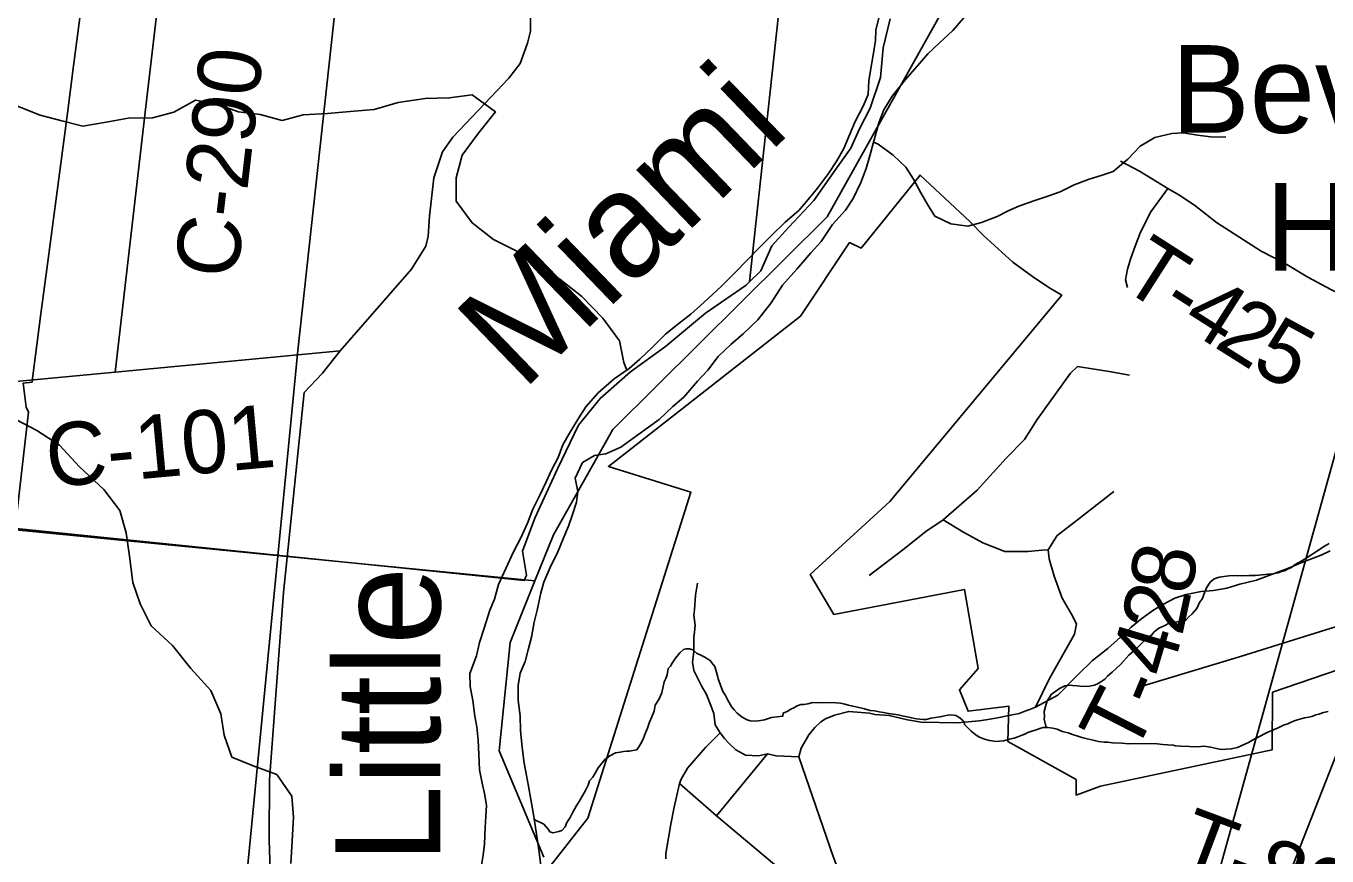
# Model space of a CAD drawing. Extents: x 44.2 to 78.2, y 4.5 to 26.5.
# Drawn here: x 49.189 to 50.361, y 22.487 to 23.234 of the extents above; entities that cross this region are included whole.
import ezdxf

# ---------------------------------------------------------------- set-up
doc = ezdxf.new("R2010")
doc.units = 0
for name, color, linetype in [('GM_X_City_Street', 7, 'Continuous'), ('GM_X_Corporation', 7, 'Continuous'), ('GM_X_County_Road', 7, 'Continuous'), ('GM_X_County_Road_Text', 7, 'Continuous'), ('GM_X_Interstate_Route', 7, 'Continuous'), ('GM_X_Major_River', 7, 'Continuous'), ('GM_X_Major_River_Text', 7, 'Continuous'), ('GM_X_Minor_River', 7, 'Continuous'), ('GM_X_Rail_Line', 7, 'Continuous'), ('GM_X_Section', 7, 'Continuous'), ('GM_X_State_Route', 7, 'Continuous'), ('GM_X_Township_Road', 7, 'Continuous'), ('GM_X_Township_Road_Text', 7, 'Continuous'), ('GM_X_Unincorporated_Text', 7, 'Continuous'), ('SH_Cut_Line', 7, 'Continuous'), ('SH_Data', 7, 'Continuous')]:
    doc.layers.add(name, color=color, linetype=linetype)

msp = doc.modelspace()

# ---------------------------------------------------------------- linework, layer by layer
at = {"layer": 'GM_X_City_Street'}
msp.add_line((49.8105, 22.5227), (49.8565, 22.5786), dxfattribs=at)
for points in [[(49.8849, 22.5759), (49.8643, 22.5767), (49.8565, 22.5786), (49.8485, 22.5768), (49.8366, 22.5774), (49.828, 22.582), (49.8215, 22.5883), (49.8177, 22.5923), (49.8138, 22.5974), (49.8094, 22.6046), (49.8083, 22.6148), (49.8055, 22.622), (49.8017, 22.632), (49.797, 22.6399), (49.7901, 22.6537), (49.7889, 22.6612), (49.7901, 22.6703), (49.7901, 22.6832), (49.7908, 22.6885), (49.7914, 22.6942), (49.7901, 22.7033), (49.7908, 22.7083), (49.7917, 22.7215), (49.7936, 22.7321)], [(49.765, 22.484), (49.765, 22.4866), (49.7651, 22.4887), (49.7695, 22.5153), (49.7724, 22.5306), (49.7773, 22.5519), (49.7787, 22.5558), (49.7844, 22.5656), (49.7923, 22.5747), (49.8009, 22.5844), (49.8138, 22.5974)], [(49.9367, 22.4306), (49.9156, 22.4861), (49.8849, 22.5759)], [(49.8798, 22.4648), (49.8105, 22.5227), (49.7773, 22.5519)]]:
    msp.add_lwpolyline(points, dxfattribs=at)
at = {"layer": 'GM_X_Corporation'}
msp.add_lwpolyline([(49.6269, 22.4341), (49.6947, 22.5207), (49.7875, 22.8141), (49.7133, 22.8372), (49.8862, 22.9727), (49.9305, 23.039), (49.9408, 23.034), (49.994, 23.0998), (50.0389, 23.0579), (50.0512, 23.0452), (50.0777, 23.0214), (50.0953, 23.0083), (50.11, 22.9986), (50.1216, 22.9917), (49.9668, 22.8059), (49.895, 22.7401), (49.9162, 22.7041), (50.0341, 22.7264), (50.0463, 22.6553), (50.0294, 22.6361), (50.0372, 22.6168), (50.0741, 22.6214), (50.0731, 22.5895), (50.1347, 22.5553), (50.1346, 22.5413), (50.1565, 22.5494), (50.3111, 22.582), (50.3116, 22.634), (50.3836, 22.6588)], dxfattribs=at)
at = {"layer": 'GM_X_County_Road'}
for points in [[(49.2689, 22.9223), (49.2965, 23.1616), (49.3169, 23.3355), (49.3208, 23.3684), (49.3292, 23.4402), (49.3295, 23.4424), (49.3374, 23.5063), (49.3403, 23.5298), (49.3454, 23.5703)], [(49.1987, 22.9157), (49.2689, 22.9223), (49.4717, 22.9416)], [(49.0413, 22.9008), (49.1987, 22.9157)], [(50.0894, 22.6171), (50.092, 22.6181), (50.098, 22.6206), (50.118, 22.6314), (50.1362, 22.6497), (50.1494, 22.6627), (50.1632, 22.6734), (50.1745, 22.6835), (50.1842, 22.6926), (50.1927, 22.6995), (50.2037, 22.7076), (50.2134, 22.7133), (50.2234, 22.7186), (50.2338, 22.7221), (50.2473, 22.7246), (50.2583, 22.7255), (50.2702, 22.7277), (50.2821, 22.7312), (50.2972, 22.7349), (50.3107, 22.74), (50.3245, 22.745), (50.3395, 22.7513), (50.3552, 22.7575), (50.3634, 22.7613)], [(49.8849, 22.5759), (49.8868, 22.5837), (49.8937, 22.5956), (49.8993, 22.6022), (49.9047, 22.6072), (49.9087, 22.6101), (49.9169, 22.6132), (49.9298, 22.6167), (49.9483, 22.615), (49.9532, 22.614), (49.9662, 22.6129), (49.9828, 22.6091), (49.995, 22.6069), (50.0276, 22.6063), (50.0473, 22.6081), (50.0533, 22.609), (50.0622, 22.6106), (50.0755, 22.6132), (50.0834, 22.6148), (50.0894, 22.6171)]]:
    msp.add_lwpolyline(points, dxfattribs=at)
at = {"layer": 'GM_X_Interstate_Route'}
msp.add_lwpolyline([(49.1786, 22.7786), (49.1909, 22.8861), (49.1887, 22.8907), (49.1861, 22.9124), (49.194, 22.9133), (49.1948, 22.9189), (49.202, 22.9747), (49.2079, 23.0194), (49.216, 23.0809), (49.2259, 23.1554), (49.2315, 23.1982), (49.2488, 23.3306)], dxfattribs=at)
at = {"layer": 'GM_X_Major_River'}
for points in [[(49.957, 23.2425), (49.9541, 23.2304), (49.9539, 23.2209), (49.9517, 23.2076), (49.9492, 23.194), (49.9478, 23.1845), (49.9472, 23.1723), (49.9428, 23.1618), (49.9356, 23.1479), (49.9308, 23.1366), (49.9252, 23.1238), (49.9189, 23.1125), (49.9115, 23.1012), (49.9017, 23.0881), (49.8931, 23.0777), (49.8849, 23.0679), (49.8725, 23.0572), (49.8601, 23.0453), (49.8504, 23.0356), (49.8376, 23.0225), (49.8279, 23.0125), (49.8151, 22.9998), (49.7992, 22.9849), (49.7876, 22.9745), (49.7756, 22.9653), (49.7648, 22.9564), (49.7528, 22.9444), (49.7416, 22.934), (49.7319, 22.9255), (49.7184, 22.9163), (49.7041, 22.9036), (49.6928, 22.8909), (49.6865, 22.8812), (49.6782, 22.8673), (49.6723, 22.8568), (49.6679, 22.8454), (49.6623, 22.8345), (49.6572, 22.8236), (49.6512, 22.8108), (49.6452, 22.7988), (49.6404, 22.7863), (49.6344, 22.7731), (49.6277, 22.7604), (49.6209, 22.7453), (49.6142, 22.731), (49.6105, 22.7178), (49.6064, 22.708), (49.6012, 22.6917), (49.5971, 22.6789), (49.5945, 22.6668), (49.5885, 22.6509), (49.5886, 22.6391), (49.591, 22.6265), (49.593, 22.6124), (49.5947, 22.6029), (49.5959, 22.5907), (49.5964, 22.5778), (49.5972, 22.5641), (49.5996, 22.5522), (49.6017, 22.5427), (49.6034, 22.5324), (49.6028, 22.5221), (49.6022, 22.5126), (49.6015, 22.4971), (49.6005, 22.4872), (49.5983, 22.4747)], [(49.6526, 22.4755), (49.6507, 22.4919), (49.6491, 22.5022), (49.6477, 22.5121), (49.6454, 22.5258), (49.6434, 22.5373), (49.6413, 22.5495), (49.6393, 22.559), (49.6372, 22.5701), (49.6356, 22.5842), (49.6341, 22.5994), (49.6336, 22.6127), (49.632, 22.6264), (49.6319, 22.6401), (49.6337, 22.6511), (49.6381, 22.6617), (49.641, 22.6723), (49.6439, 22.6836), (49.6465, 22.6972), (49.649, 22.7078), (49.6523, 22.7234), (49.6552, 22.7332), (49.6616, 22.7483), (49.6671, 22.7588), (49.6732, 22.7735), (49.6772, 22.7837), (49.6808, 22.7942), (49.6845, 22.8052), (49.6858, 22.8147), (49.6834, 22.8269), (49.6898, 22.8408), (49.7006, 22.8471), (49.7109, 22.8487), (49.7243, 22.8546), (49.7343, 22.8619), (49.759, 22.8797), (49.7714, 22.8912), (49.7811, 22.8998), (49.7935, 22.914), (49.8028, 22.924), (49.8122, 22.9364), (49.8235, 22.9472), (49.8347, 22.9568), (49.8479, 22.9695), (49.86, 22.9848), (49.8702, 23.0006), (49.883, 23.0151), (49.8955, 23.0297), (49.9048, 23.0398), (49.915, 23.0552), (49.9267, 23.0682), (49.9338, 23.0787), (49.9405, 23.093), (49.9453, 23.1058), (49.9486, 23.1172), (49.9527, 23.1315), (49.9569, 23.1467), (49.9613, 23.1584), (49.9688, 23.1708), (49.9809, 23.1857), (49.9918, 23.198), (50.0011, 23.2089), (50.0112, 23.2185), (50.0236, 23.2301), (50.0349, 23.2431)]]:
    msp.add_lwpolyline(points, dxfattribs=at)
at = {"layer": 'GM_X_Minor_River'}
for points in [[(49.7298, 22.9241), (49.727, 22.9311), (49.7232, 22.9505), (49.7083, 22.971), (49.6892, 22.9904), (49.6694, 23.006), (49.65, 23.0186), (49.6294, 23.0319), (49.6096, 23.0418), (49.5905, 23.0566), (49.576, 23.0764), (49.576, 23.0973), (49.5814, 23.1178), (49.5958, 23.1372), (49.6115, 23.1566), (49.5905, 23.1719), (49.5699, 23.1692), (49.5482, 23.1688), (49.5238, 23.165), (49.5021, 23.1589), (49.4807, 23.157), (49.4602, 23.1551), (49.4384, 23.154), (49.4194, 23.149), (49.3996, 23.1544), (49.3801, 23.1566), (49.3607, 23.1635), (49.3413, 23.1673), (49.3218, 23.1563), (49.3024, 23.1513), (49.2807, 23.1509), (49.2608, 23.1475), (49.2399, 23.1437), (49.2208, 23.1487), (49.2014, 23.1536), (49.1793, 23.1624)], [(49.9521, 23.1293), (49.9562, 23.1275), (49.9697, 23.1177), (49.9813, 23.1069), (49.9882, 23.0961), (49.9948, 23.0838), (50.0014, 23.0723), (50.0073, 23.0627), (50.0216, 23.0559), (50.0371, 23.0537), (50.0494, 23.0569), (50.0635, 23.0623), (50.0735, 23.0675), (50.0831, 23.0718), (50.0965, 23.0765), (50.1091, 23.0808), (50.1202, 23.0848), (50.1329, 23.091), (50.1463, 23.0961), (50.157, 23.0993), (50.168, 23.1029), (50.1812, 23.114), (50.1924, 23.1259), (50.2055, 23.1337), (50.2208, 23.1372), (50.231, 23.1377), (50.2439, 23.1356), (50.256, 23.1342), (50.2693, 23.134)], [(49.4271, 22.4796), (49.4282, 22.5001), (49.4294, 22.5214), (49.4279, 22.5404), (49.4145, 22.5598), (49.3932, 22.5678), (49.3741, 22.5754), (49.3672, 22.5952), (49.3642, 22.6146), (49.355, 22.6355), (49.3371, 22.6553), (49.3204, 22.6762), (49.3013, 22.6937), (49.2914, 22.7135), (49.2849, 22.7329), (49.2819, 22.7565), (49.2788, 22.7774), (49.2731, 22.7976), (49.2586, 22.8166), (49.2369, 22.8371), (49.2186, 22.8565), (49.1984, 22.8698), (49.1793, 22.8797)], [(50.1077, 22.6021), (50.1059, 22.6097), (50.106, 22.612), (50.1057, 22.6166), (50.107, 22.6211), (50.1086, 22.6263), (50.111, 22.6297), (50.1122, 22.6319), (50.1195, 22.6374), (50.1245, 22.6396), (50.1276, 22.6403), (50.1314, 22.6402), (50.1355, 22.6397), (50.1405, 22.6392), (50.1466, 22.6394), (50.1511, 22.6404), (50.1538, 22.6415), (50.1569, 22.6433), (50.1604, 22.6458), (50.1627, 22.6484), (50.167, 22.6521), (50.1744, 22.6591), (50.1822, 22.6673), (50.1869, 22.6717), (50.19, 22.6743), (50.1931, 22.6776), (50.1966, 22.6809), (50.2001, 22.6839), (50.2024, 22.6853), (50.2048, 22.6883), (50.209, 22.6916), (50.2144, 22.6941), (50.2179, 22.6959), (50.2224, 22.6969), (50.227, 22.6976), (50.2312, 22.6982), (50.2335, 22.6989), (50.2359, 22.7015), (50.239, 22.7045), (50.2433, 22.7093), (50.2461, 22.7153), (50.248, 22.7179), (50.2505, 22.7243), (50.2521, 22.728), (50.2553, 22.7332), (50.2588, 22.7362), (50.2634, 22.7376), (50.2675, 22.7382), (50.2721, 22.7389), (50.2778, 22.7391), (50.2843, 22.7389), (50.2904, 22.7391), (50.2961, 22.739), (50.3021, 22.7396), (50.3079, 22.7402), (50.312, 22.7405), (50.3162, 22.7415), (50.3197, 22.7426), (50.3224, 22.7432), (50.3251, 22.7447), (50.3281, 22.7461), (50.332, 22.7491), (50.3378, 22.7523), (50.3428, 22.7552), (50.347, 22.7581), (50.3505, 22.7603), (50.3582, 22.7654), (50.3625, 22.768)], [(49.6465, 22.5195), (49.655, 22.5153), (49.659, 22.5107), (49.6605, 22.5084), (49.6631, 22.5075), (49.6685, 22.5085), (49.6712, 22.5096), (49.6743, 22.5129), (49.6759, 22.5167), (49.6787, 22.5212), (49.6811, 22.526), (49.6842, 22.5313), (49.687, 22.5357), (49.6926, 22.5455), (49.695, 22.5503), (49.6962, 22.5541), (49.6993, 22.5574), (49.7013, 22.5612), (49.7041, 22.566), (49.71, 22.5734), (49.7146, 22.5767), (49.7196, 22.5793), (49.7238, 22.5799), (49.7269, 22.5806), (49.7299, 22.5809), (49.7322, 22.5808), (49.7353, 22.5815), (49.7387, 22.5822), (49.7407, 22.5848), (49.7434, 22.5893), (49.7447, 22.5926), (49.7467, 22.5975), (49.7483, 22.6016), (49.7503, 22.6069), (49.7524, 22.6118), (49.7544, 22.617), (49.7553, 22.6223), (49.7588, 22.6275), (49.7613, 22.6335), (49.7634, 22.6433), (49.765, 22.6463), (49.7662, 22.6497), (49.7671, 22.6554), (49.7691, 22.6576), (49.7707, 22.6602), (49.7738, 22.6647), (49.7777, 22.6695), (49.7809, 22.6725), (49.7832, 22.6732), (49.7862, 22.6731), (49.7892, 22.6722), (49.7925, 22.6691), (49.7971, 22.6671), (49.8001, 22.6655), (49.8027, 22.6639), (49.8049, 22.6627), (49.8064, 22.6604), (49.809, 22.6573), (49.8097, 22.655), (49.8107, 22.652), (49.8114, 22.6489), (49.8121, 22.6462), (49.8164, 22.6347), (49.8186, 22.6309), (49.8207, 22.6267), (49.8244, 22.6205), (49.8266, 22.6182), (49.8292, 22.6151), (49.8336, 22.6115), (49.8381, 22.6092), (49.8408, 22.6083), (49.8446, 22.6078), (49.8484, 22.6081), (49.8537, 22.6091), (49.8602, 22.6112), (49.8705, 22.6125), (49.8706, 22.6151), (49.8748, 22.6169), (49.8771, 22.6184), (49.8809, 22.6202), (49.8833, 22.6216), (49.8867, 22.623), (49.8894, 22.623), (49.8928, 22.6236), (49.8974, 22.6247), (49.9023, 22.6245), (49.9054, 22.6248), (49.9187, 22.6245), (49.9224, 22.624), (49.9262, 22.6232), (49.9296, 22.6223), (49.9334, 22.6214), (49.9402, 22.6198), (49.944, 22.6189), (49.9489, 22.6176), (49.953, 22.6171), (49.9572, 22.6163), (49.961, 22.6158), (49.9655, 22.6149), (49.9697, 22.6141), (49.9742, 22.6136)], [(49.9742, 22.6136), (49.978, 22.6127), (49.9825, 22.6118), (49.9863, 22.611), (49.9908, 22.6101), (49.9969, 22.6095), (49.9996, 22.6095), (50.0041, 22.6105), (50.0118, 22.6118), (50.0206, 22.6135), (50.024, 22.6134), (50.0262, 22.613), (50.0289, 22.6114), (50.0315, 22.6094), (50.0337, 22.6071), (50.034, 22.6048), (50.0362, 22.6028), (50.0399, 22.5989), (50.0444, 22.5954), (50.0474, 22.5934), (50.0519, 22.5918), (50.0564, 22.5906), (50.0625, 22.5896), (50.0655, 22.5899), (50.0693, 22.5902), (50.0747, 22.5916), (50.0789, 22.5926), (50.082, 22.5937), (50.085, 22.5951), (50.0889, 22.5965), (50.0912, 22.5976), (50.0939, 22.5987), (50.0985, 22.6001), (50.1027, 22.6015), (50.105, 22.6022), (50.1091, 22.6021), (50.1137, 22.6016), (50.1175, 22.6007), (50.122, 22.5987), (50.1273, 22.5974), (50.1314, 22.5958), (50.1352, 22.5946), (50.1397, 22.5933), (50.1446, 22.592), (50.1499, 22.5908), (50.1548, 22.5895), (50.1597, 22.589), (50.1631, 22.5889), (50.1673, 22.5884), (50.1756, 22.5882), (50.1821, 22.5876), (50.1878, 22.5879), (50.2075, 22.5874), (50.2128, 22.5868), (50.217, 22.5867), (50.2219, 22.5862), (50.2242, 22.5858), (50.2287, 22.5853), (50.2447, 22.5849), (50.247, 22.5852), (50.2496, 22.5855), (50.2557, 22.5846), (50.261, 22.5833), (50.2651, 22.5824), (50.2697, 22.5827), (50.2743, 22.583), (50.28, 22.5843), (50.2838, 22.5861), (50.2873, 22.5875), (50.29, 22.5886), (50.2935, 22.5908), (50.2973, 22.593), (50.3073, 22.598), (50.3165, 22.6019), (50.3219, 22.6045), (50.3254, 22.6055), (50.3284, 22.6069), (50.3319, 22.6084), (50.3361, 22.6098), (50.3403, 22.6108), (50.3441, 22.6115), (50.3479, 22.6125), (50.3506, 22.6136), (50.3533, 22.6143), (50.3575, 22.6157), (50.3617, 22.6167)]]:
    msp.add_lwpolyline(points, dxfattribs=at)
at = {"layer": 'GM_X_Rail_Line'}
for points in [[(49.3823, 22.417), (49.4335, 22.9419), (49.5157, 23.6948), (49.5516, 23.9481), (49.5607, 24.0404), (49.5582, 24.101), (49.5479, 24.1577), (49.5234, 24.2196), (49.4858, 24.2792), (49.3949, 24.3999)], [(47.6333, 22.932), (49.4237, 22.7563), (49.647, 22.7343), (49.6637, 22.7757), (49.7173, 22.8707), (49.9104, 23.0622), (50.0184, 23.2552)], [(50.0184, 23.2552), (49.9104, 23.0622), (49.7173, 22.8707), (49.6637, 22.7757), (49.647, 22.7343), (49.6246, 22.6788), (49.6147, 22.5812), (49.655, 22.4854)], [(49.655, 22.4854), (49.6147, 22.5812), (49.6246, 22.6788), (49.647, 22.7343), (49.4237, 22.7563), (47.6333, 22.932), (46.627, 23.0248), (46.3359, 23.0552), (46.3359, 19.3655)]]:
    msp.add_lwpolyline(points, dxfattribs=at)
at = {"layer": 'GM_X_Section'}
msp.add_lwpolyline([(48.7465, 23.8538), (49.9184, 23.7227), (49.8403, 23.0036), (49.8372, 23.0006), (49.8007, 22.9753), (49.7648, 22.9454), (49.7332, 22.9224), (49.7059, 22.8985), (49.6863, 22.8746), (49.6675, 22.8353), (49.647, 22.7909), (49.6359, 22.761), (49.6394, 22.7393), (49.6374, 22.7347), (48.6514, 22.8354)], close=True, dxfattribs=at)
msp.add_lwpolyline([(49.967, 23.2404), (49.9608, 23.2144), (49.9584, 23.1875), (49.9491, 23.16), (49.9392, 23.1409), (49.9317, 23.124), (49.9181, 23.105), (49.8982, 23.077), (49.8757, 23.0528), (49.8606, 23.0361), (49.8505, 23.0134), (49.8403, 23.0036), (49.9184, 23.7227)], dxfattribs=at)
at = {"layer": 'GM_X_State_Route'}
for points in [[(49.6431, 23.2489), (49.6429, 23.2295), (49.6402, 23.2186), (49.6336, 23.2003), (49.6235, 23.187), (49.602, 23.1641), (49.5732, 23.1338), (49.5639, 23.1206), (49.556, 23.0974), (49.5521, 23.0626), (49.5509, 23.0448), (49.5489, 23.0357), (49.5358, 23.015), (49.4717, 22.9416)], [(49.4717, 22.9416), (49.4556, 22.9214), (49.4392, 22.9039), (49.4239, 22.7557), (49.4206, 22.7237), (49.4078, 22.5555), (49.4076, 22.5011), (49.4086, 22.4737), (49.4079, 22.4509), (49.4003, 22.4227)]]:
    msp.add_lwpolyline(points, dxfattribs=at)
at = {"layer": 'GM_X_Township_Road'}
for points in [[(50.4459, 22.9631), (50.3904, 22.9835), (50.364, 22.9966), (50.3433, 23.0078), (50.3229, 23.0201), (50.3013, 23.0311), (50.2611, 23.0569), (50.2411, 23.0728), (50.2272, 23.0819), (50.2171, 23.0877), (50.1918, 23.1033), (50.1744, 23.1124)], [(50.2171, 23.0877), (50.2019, 23.0666), (50.1927, 23.0484), (50.1877, 23.0358), (50.1839, 23.0249), (50.1808, 23.0151), (50.1792, 23.0054), (50.1808, 22.9985)], [(49.9482, 22.739), (49.9785, 22.7621), (49.9991, 22.7786), (50.0147, 22.7893), (50.0455, 22.816), (50.0716, 22.8448), (50.0881, 22.8616), (50.0994, 22.8795), (50.1295, 22.9214), (50.1357, 22.9273), (50.1644, 22.9228), (50.1826, 22.9194)], [(50.098, 22.6206), (50.1106, 22.6465), (50.1264, 22.6746), (50.1332, 22.6864), (50.135, 22.6957), (50.1304, 22.7042), (50.1221, 22.7188), (50.1149, 22.7385), (50.1103, 22.7541), (50.1093, 22.7621), (50.1176, 22.7751), (50.1342, 22.788), (50.1686, 22.8148)], [(50.1093, 22.7621), (50.1037, 22.7619), (50.0914, 22.7608), (50.0703, 22.7607), (50.0505, 22.7684), (50.0326, 22.7783), (50.0147, 22.7893)], [(50.3738, 22.6946), (50.2825, 22.6663), (50.192, 22.6387)]]:
    msp.add_lwpolyline(points, dxfattribs=at)
at = {"layer": 'SH_Cut_Line'}
for points in [[(49.655, 22.4854), (49.6147, 22.5812), (49.6246, 22.6788), (49.647, 22.7343), (49.6637, 22.7757), (49.7173, 22.8707), (49.9104, 23.0622), (50.0184, 23.2552)], [(50.0184, 23.2552), (49.9104, 23.0622), (49.7173, 22.8707), (49.6637, 22.7757), (49.647, 22.7343), (49.6246, 22.6788), (49.6147, 22.5812), (49.655, 22.4854)]]:
    msp.add_lwpolyline(points, dxfattribs=at)
at = {"layer": 'SH_Data'}
msp.add_lwpolyline([(50.6141, 23.7345), (50.1075, 21.9122), (50.6141, 23.202)], close=True, dxfattribs=at)

# ---------------------------------------------------------------- texts
at = {"layer": 'GM_X_County_Road_Text'}
for s, rotation, p in [('C-290', 83.387, (49.3786, 23.0052)), ('C-101', 5.2452, (49.209, 22.8183))]:
    msp.add_text(s, height=0.05682, rotation=rotation, dxfattribs=at).set_placement(p)
at = {"layer": 'GM_X_Major_River_Text'}
for s, rotation, p in [('Miami', 43.9949, (49.6358, 22.9044)), ('Little', 90.0081, (49.5618, 22.4796))]:
    msp.add_text(s, height=0.09467, rotation=rotation, dxfattribs=at).set_placement(p)
at = {"layer": 'GM_X_Township_Road_Text'}
for s, height, rotation, p in [('T', 0.0568, 327.3845, (50.1723, 23.0001)), ('-', 0.0568, 327.4107, (50.2082, 22.9772)), ('4', 0.0568, 327.5006, (50.2279, 22.9645)), ('2', 0.0568, 327.8313, (50.2577, 22.9456)), ('5', 0.0568, 331.3848, (50.2907, 22.925)), ('8', 0.0568, 80.2847, (50.2379, 22.7204)), ('2', 0.0568, 77.791, (50.2299, 22.6835)), ('4', 0.0568, 73.4204, (50.2188, 22.6454)), ('-', 0.0568, 67.5491, (50.2078, 22.6179)), ('T', 0.0568, 62.8542, (50.1862, 22.5754)), ('T-82', 0.05682, 339.387, (50.2219, 22.4776))]:
    msp.add_text(s, height=height, rotation=rotation, dxfattribs=at).set_placement(p)
at = {"layer": 'GM_X_Unincorporated_Text'}
for s, p in [('Beverly', (50.2205, 23.1378)), ('Hills', (50.3055, 23.0137))]:
    msp.add_text(s, height=0.07898, rotation=0, dxfattribs=at).set_placement(p)

doc.saveas('drawing.dxf')
